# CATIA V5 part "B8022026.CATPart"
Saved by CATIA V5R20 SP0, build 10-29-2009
Part number: B8022026
Revision: 5
Definition: design
Nomenclature: B8022026
Source: made
Description: NOT SPECIFIED
Bounding box of the stored display mesh (mm): x -18 to 18, y -18 to 18, z -9 to 26
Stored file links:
  C:\Users\Utente\Desktop\3D files B802\B8022026.CATPart
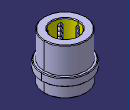
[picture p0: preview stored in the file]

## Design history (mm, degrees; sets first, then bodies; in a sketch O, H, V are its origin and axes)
Body1 "MANIFOLD_SOLID_BREP #38" (main body)
  Solid1: solid without history
Body2 "MANIFOLD_SOLID_BREP #76"
  Solid2: solid without history
Body3 "MANIFOLD_SOLID_BREP #114"
  Solid3: solid without history
Body4 "MANIFOLD_SOLID_BREP #152"
  Solid4: solid without history
Body5 "MANIFOLD_SOLID_BREP #190"
  Solid5: solid without history
Body6 "MANIFOLD_SOLID_BREP #228"
  Solid6: solid without history
Body7 "MANIFOLD_SOLID_BREP #266"
  Solid7: solid without history
Body8 "MANIFOLD_SOLID_BREP #304"
  Solid8: solid without history
Body9 "MANIFOLD_SOLID_BREP #2006"
  Solid9: solid without history
Body10 "MANIFOLD_SOLID_BREP #2044"
  Solid10: solid without history
Body11 "MANIFOLD_SOLID_BREP #2082"
  Solid11: solid without history
Body12 "MANIFOLD_SOLID_BREP #2120"
  Solid12: solid without history
Body13 "MANIFOLD_SOLID_BREP #2158"
  Solid13: solid without history
Body14 "MANIFOLD_SOLID_BREP #2196"
  Solid14: solid without history
Body15 "MANIFOLD_SOLID_BREP #2234"
  Solid15: solid without history
Body16 "MANIFOLD_SOLID_BREP #2272"
  Solid16: solid without history
Body17 "MANIFOLD_SOLID_BREP #2310"
  Solid17: solid without history
Body18 "MANIFOLD_SOLID_BREP #2348"
  Solid18: solid without history
Body19 "MANIFOLD_SOLID_BREP #2386"
  Solid19: solid without history
Body20 "MANIFOLD_SOLID_BREP #2424"
  Solid20: solid without history
Body21 "MANIFOLD_SOLID_BREP #2462"
  Solid21: solid without history
Body22 "MANIFOLD_SOLID_BREP #2500"
  Solid22: solid without history
Body23 "MANIFOLD_SOLID_BREP #2538"
  Solid23: solid without history
Body24 "MANIFOLD_SOLID_BREP #2576"
  Solid24: solid without history
Body25 "MANIFOLD_SOLID_BREP #2614"
  Solid25: solid without history
Body26 "MANIFOLD_SOLID_BREP #2652"
  Solid26: solid without history
Body27 "MANIFOLD_SOLID_BREP #2690"
  Solid27: solid without history
Body28 "MANIFOLD_SOLID_BREP #2728"
  Solid28: solid without history
Body29 "MANIFOLD_SOLID_BREP #2766"
  Solid29: solid without history
Body30 "MANIFOLD_SOLID_BREP #2804"
  Solid30: solid without history
Body31 "MANIFOLD_SOLID_BREP #2842"
  Solid31: solid without history
Body32 "MANIFOLD_SOLID_BREP #2880"
  Solid32: solid without history
Body33 "MANIFOLD_SOLID_BREP #2918"
  Solid33: solid without history
Body34 "MANIFOLD_SOLID_BREP #2956"
  Solid34: solid without history
Body35 "MANIFOLD_SOLID_BREP #2994"
  Solid35: solid without history
Body36 "MANIFOLD_SOLID_BREP #3032"
  Solid36: solid without history
Body37 "MANIFOLD_SOLID_BREP #3070"
  Solid37: solid without history
Body38 "MANIFOLD_SOLID_BREP #3108"
  Solid38: solid without history
Body39 "MANIFOLD_SOLID_BREP #3146"
  Solid39: solid without history
Body40 "MANIFOLD_SOLID_BREP #3184"
  Solid40: solid without history
Body41 "MANIFOLD_SOLID_BREP #3222"
  Solid41: solid without history
Body42 "MANIFOLD_SOLID_BREP #3260"
  Solid42: solid without history
Body43 "MANIFOLD_SOLID_BREP #3298"
  Solid43: solid without history
Body44 "MANIFOLD_SOLID_BREP #3336"
  Solid44: solid without history
Body45 "MANIFOLD_SOLID_BREP #3374"
  Solid45: solid without history
Body46 "MANIFOLD_SOLID_BREP #3412"
  Solid46: solid without history
Body47 "MANIFOLD_SOLID_BREP #3450"
  Solid47: solid without history
Body48 "MANIFOLD_SOLID_BREP #3488"
  Solid48: solid without history
Body49 "MANIFOLD_SOLID_BREP #3526"
  Solid49: solid without history
Body50 "MANIFOLD_SOLID_BREP #3564"
  Solid50: solid without history
Body51 "MANIFOLD_SOLID_BREP #3602"
  Solid51: solid without history
Body52 "MANIFOLD_SOLID_BREP #3640"
  Solid52: solid without history
Body53 "MANIFOLD_SOLID_BREP #3678"
  Solid53: solid without history
Body54 "MANIFOLD_SOLID_BREP #3716"
  Solid54: solid without history
Body55 "MANIFOLD_SOLID_BREP #3754"
  Solid55: solid without history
